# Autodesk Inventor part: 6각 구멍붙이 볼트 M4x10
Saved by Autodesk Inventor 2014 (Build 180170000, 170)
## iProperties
Created: 2026-04
Part Number: 6각 구멍붙이 볼트 M4x10
Material: 일반
Document SubType Name: Modeling
Designer: dg
Density: 1 g/cm^3
Appearance: 기본값
Author: dg
Author: jhkim
Description: 6각머리 태핑 나사
Creation Date: 2026-03-27
Sending System: Autodesk Inventor 2026
Preprocessor: ST-DEVELOPER v20.1
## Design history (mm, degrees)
node "6각 구멍붙이 볼트 M4x101"
body "Solid1"
node "기준1"
